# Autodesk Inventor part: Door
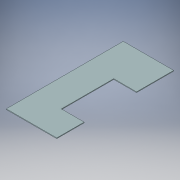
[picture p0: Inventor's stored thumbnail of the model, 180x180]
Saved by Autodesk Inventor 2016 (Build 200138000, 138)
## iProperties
Created: 2016-01
Part Number: Door
Material: Generic
Document SubType Name: Modeling
Designer: John
Density: 1 g/cm^3
Appearance: Default
Author: John
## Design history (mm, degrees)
feature "Base1"
sketch "Sketch1"
  geometry: L1 (71, -250)-(71, -512.7) reference; L2 (221, -150)-(171, -150) reference; L3 (221, 0)-(221, -150) reference; L4 (0, 0)-(221, 0) reference; L5 (0, -512.7)-(0, 0) reference; L6 (71, -512.7)-(0, -512.7) reference; L7 (221, -150)-(71, -150); L8 (71, -150)-(71, -512.7); L9 (71, -512.7)-(221, -512.7); L10 (221, -512.7)-(221, -150); A1 r 100 centre (171, -250) between (171, -150) and (71, -250) reference; 1 further point
  constraints: 8 end point, 2 parallel, 1 horizontal, 1 perpendicular
extrude "Extrusion1" join sketch "Sketch1" stored distance "d0" = 10; taper "d1" = 0 deg
sketch "Sketch2"
  geometry: L1 (121, 120)-(221, 120); L2 (221, 120)-(221, 350); L3 (221, 350)-(121, 350); L4 (121, 350)-(121, 120); L5 (0, 0)-(221, 0) reference; L6 (221, 0)-(221, 512.7) reference; L7 (0, 512.7)-(221, 512.7) reference; L8 (0, 0)-(0, 512.7) reference; 1 further point
  constraints: 8 end point, 2 parallel, 1 horizontal, 1 perpendicular, 1 point on line
  dimensions: "d2" = 230 distance of L3.end L1.start; "d3" = 100 distance of L1.start L1.end; "d4" = 120 distance between parallel lines of L5 L1; "d5" = 162.7 distance between parallel lines of L7 L3 (derived)
extrude "Extrusion2" cut sketch "Sketch2" stored distance "d6" = 10; taper "d7" = 0 deg
body "Solid1"
node "Projected Loop1"
node "Projected Loop2"
